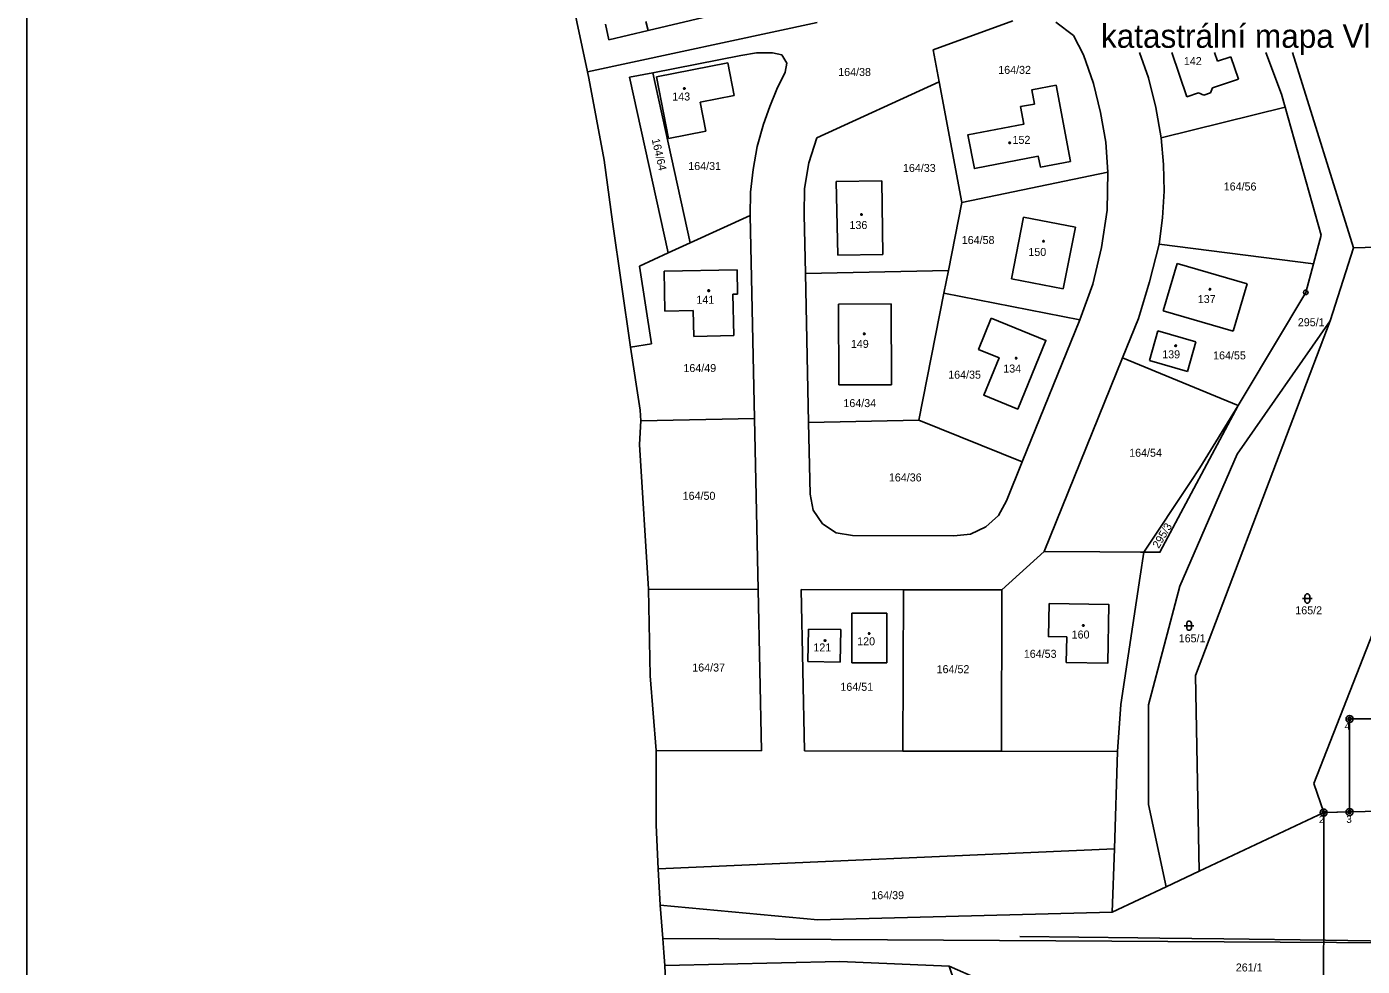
# Model space of a CAD drawing. Extents: x -779723 to -777378, y -1011169 to -1009297.
# Drawn here: x -779530.7 to -779247, y -1010479.3 to -1010279.6 of the extents above; entities that cross this region are included whole.
import ezdxf

# ---------------------------------------------------------------- set-up
doc = ezdxf.new("R2010")
doc.units = 0
for name, color, linetype in [('body', 7, 'Continuous'), ('cisla', 7, 'Continuous'), ('Default', 7, 'Continuous'), ('KN_HRANICE', 7, 'Continuous'), ('KN_KULTURY', 7, 'Continuous'), ('KN_PARCELY', 7, 'Continuous'), ('KN_VEDENI', 7, 'Continuous'), ('LEGENDA', 7, 'Continuous'), ('obvod_stavby', 7, 'Continuous'), ('Železniční svršek', 7, 'Continuous')]:
    doc.layers.add(name, color=color, linetype=linetype)

# ---------------------------------------------------------------- blocks, each defined once
blk = doc.blocks.new('316')
at = {"layer": 'Default'}
for points in [[(-1, 1), (0.27, 1), (1, 1)], [(-0.5, 1.5), (-0.4, 1.79), (-0.15, 1.97), (0.16, 1.97), (0.41, 1.79), (0.51, 1.5), (0.51, 0.5), (0.41, 0.21), (0.16, 0.03), (-0.15, 0.03), (-0.4, 0.21), (-0.5, 0.5), (-0.5, 1.5)]]:
    blk.add_lwpolyline(points, dxfattribs=at)
blk = doc.blocks.new('105')
at = {"layer": 'Default'}
blk.add_line((-0.12, 0), (0.12, 0), dxfattribs=at)
blk.add_lwpolyline([(0.15, 0.48), (0.4, 0.3), (0.5, 0.01), (0.4, -0.28), (0.15, -0.46), (-0.16, -0.46), (-0.41, -0.28), (-0.51, 0.01), (-0.41, 0.3), (-0.16, 0.48), (0.15, 0.48)], dxfattribs=at)
blk = doc.blocks.new('402')
at = {"layer": 'Default'}
blk.add_lwpolyline([(0.09, 0.15), (0.18, 0), (0.09, -0.15), (-0.09, -0.15), (-0.18, 0), (-0.09, 0.15), (0.09, 0.15)], dxfattribs=at)

msp = doc.modelspace()

# ---------------------------------------------------------------- linework, layer by layer
at = {"layer": 'body'}
for p, q in [((-779249.69, -1010426.74), (-779249.69, -1010426.74)), ((-779255.18, -1010446.63), (-779255.18, -1010446.63)), ((-779249.69, -1010446.5), (-779249.69, -1010446.5))]:
    msp.add_line(p, q, dxfattribs=at)
for centre, radius in [((-779249.69, -1010426.74), 0.75), ((-779249.69, -1010426.74), 0.35), ((-779255.18, -1010446.63), 0.75), ((-779255.18, -1010446.63), 0.35), ((-779249.69, -1010446.5), 0.75), ((-779249.69, -1010446.5), 0.35)]:
    msp.add_circle(centre, radius, dxfattribs=at)
at = {"layer": 'KN_HRANICE'}
for p, q in [((-779411.57, -1010289.24), (-779423.17, -1010234.28)), ((-779362.78, -1010278.71), (-779411.57, -1010289.24)), ((-779407.72, -1010279.08), (-779406.99, -1010282.4)), ((-779399.16, -1010278.51), (-779398.69, -1010280.44)), ((-779385.75, -1010277.38), (-779398.69, -1010280.44)), ((-779321.24, -1010278.36), (-779338.14, -1010284.55)), ((-779308.36, -1010281.51), (-779312.1, -1010278.67)), ((-779398.69, -1010280.44), (-779406.99, -1010282.4)), ((-779306.17, -1010285.63), (-779308.36, -1010281.51)), ((-779379.01, -1010285.72), (-779375.64, -1010285.2)), ((-779375.64, -1010285.2), (-779372.24, -1010285.16)), ((-779372.24, -1010285.16), (-779370.29, -1010285.62)), ((-779338.14, -1010284.55), (-779336.86, -1010291.37)), ((-779292.43, -1010290.53), (-779294.28, -1010285.09)), ((-779287.42, -1010285.09), (-779284.23, -1010294.51)), ((-779277.75, -1010286.96), (-779278.38, -1010285.09)), ((-779264.13, -1010293.98), (-779267.51, -1010285.09)), ((-779248.83, -1010326.61), (-779261.84, -1010285.09)), ((-779397.7, -1010289.41), (-779379.01, -1010285.72)), ((-779396.93, -1010290.27), (-779381.75, -1010287.29)), ((-779381.75, -1010287.29), (-779380.38, -1010294.23)), ((-779370.29, -1010285.62), (-779369.18, -1010287.35)), ((-779369.18, -1010287.35), (-779369.57, -1010289.31)), ((-779304.1, -1010291.71), (-779306.17, -1010285.63)), ((-779274.91, -1010286.01), (-779277.75, -1010286.96)), ((-779273.29, -1010290.79), (-779274.91, -1010286.01)), ((-779411.29, -1010290.56), (-779411.57, -1010289.24)), ((-779408.01, -1010308), (-779411.29, -1010290.56)), ((-779389.74, -1010325.58), (-779397.7, -1010289.41)), ((-779394.32, -1010303.41), (-779396.93, -1010290.27)), ((-779369.57, -1010289.31), (-779371.31, -1010292.92)), ((-779292.43, -1010290.53), (-779290.82, -1010296.83)), ((-779278.8, -1010292.6), (-779273.29, -1010290.79)), ((-779371.31, -1010292.92), (-779372.85, -1010296.61)), ((-779336.86, -1010291.37), (-779362.87, -1010303.27)), ((-779336.86, -1010291.37), (-779332.05, -1010316.98)), ((-779302.56, -1010297.89), (-779304.1, -1010291.71)), ((-779284.23, -1010294.51), (-779281.79, -1010293.68)), ((-779281.79, -1010293.68), (-779280.65, -1010294.17)), ((-779280.65, -1010294.17), (-779279.24, -1010293.68)), ((-779279.24, -1010293.68), (-779278.8, -1010292.6)), ((-779380.38, -1010294.23), (-779387.63, -1010295.67)), ((-779387.63, -1010295.67), (-779386.44, -1010301.84)), ((-779263.36, -1010296.74), (-779264.13, -1010293.98)), ((-779372.85, -1010296.61), (-779374.18, -1010300.38)), ((-779301.46, -1010304.17), (-779302.56, -1010297.89)), ((-779290.82, -1010296.83), (-779289.73, -1010303.24)), ((-779263.36, -1010296.74), (-779289.73, -1010303.24)), ((-779255.74, -1010323.95), (-779263.36, -1010296.74)), ((-779386.44, -1010301.84), (-779394.32, -1010303.41)), ((-779374.18, -1010300.38), (-779375.49, -1010305.12)), ((-779362.87, -1010303.27), (-779364.55, -1010308.53)), ((-779301, -1010310.57), (-779301.46, -1010304.17)), ((-779289.73, -1010303.24), (-779289.19, -1010308.89)), ((-779375.49, -1010305.12), (-779376.4, -1010309.95)), ((-779406.22, -1010321.12), (-779408.01, -1010308)), ((-779376.4, -1010309.95), (-779376.91, -1010314.83)), ((-779364.55, -1010308.53), (-779365.44, -1010313.99)), ((-779332.05, -1010316.98), (-779301, -1010310.57)), ((-779301.2, -1010318.61), (-779301, -1010310.57)), ((-779289.19, -1010308.89), (-779289.09, -1010314.57)), ((-779358.71, -1010312.55), (-779349.07, -1010312.38)), ((-779358.39, -1010328.18), (-779358.71, -1010312.55)), ((-779349.07, -1010312.38), (-779348.8, -1010328.01)), ((-779376.91, -1010314.83), (-779376.98, -1010319.73)), ((-779365.44, -1010313.99), (-779365.52, -1010319.51)), ((-779289.09, -1010314.57), (-779289.42, -1010320.24)), ((-779334.89, -1010331.42), (-779332.05, -1010316.98)), ((-779302.4, -1010326.55), (-779301.2, -1010318.61)), ((-779402.4, -1010347.73), (-779406.22, -1010321.12)), ((-779376.98, -1010319.73), (-779389.74, -1010325.58)), ((-779376.98, -1010319.73), (-779376.08, -1010362.91)), ((-779365.52, -1010319.51), (-779365.26, -1010332.05)), ((-779321.5, -1010333.19), (-779318.95, -1010320.1)), ((-779318.95, -1010320.1), (-779307.92, -1010322.25)), ((-779289.42, -1010320.24), (-779290.15, -1010325.87)), ((-779307.92, -1010322.25), (-779310.5, -1010335.33)), ((-779257.37, -1010330.02), (-779255.74, -1010323.95)), ((-779400.48, -1010330.51), (-779394.39, -1010327.71)), ((-779394.39, -1010327.71), (-779389.74, -1010325.58)), ((-779304.22, -1010334.38), (-779302.4, -1010326.55)), ((-779290.15, -1010325.87), (-779292.21, -1010333.83)), ((-779257.37, -1010330.02), (-779290.15, -1010325.87)), ((-779253.82, -1010342.15), (-779248.83, -1010326.61)), ((-779248.83, -1010326.61), (-779241.34, -1010326.4)), ((-779397.95, -1010347.05), (-779400.48, -1010330.51)), ((-779348.8, -1010328.01), (-779358.39, -1010328.18)), ((-779289.25, -1010340.01), (-779286.34, -1010329.98)), ((-779286.34, -1010329.98), (-779271.46, -1010334.31)), ((-779259, -1010336.11), (-779257.37, -1010330.02)), ((-779395.24, -1010331.56), (-779379.78, -1010331.29)), ((-779395.11, -1010340.07), (-779395.24, -1010331.56)), ((-779379.78, -1010331.29), (-779379.66, -1010336.48)), ((-779365.26, -1010332.05), (-779334.89, -1010331.42)), ((-779365.26, -1010332.05), (-779364.6, -1010363.75)), ((-779335.84, -1010336.25), (-779334.89, -1010331.42)), ((-779310.5, -1010335.33), (-779321.5, -1010333.19)), ((-779341.15, -1010363.28), (-779335.84, -1010336.25)), ((-779335.84, -1010336.25), (-779307.01, -1010341.91)), ((-779307.01, -1010341.91), (-779304.22, -1010334.38)), ((-779292.21, -1010333.83), (-779294.54, -1010341.64)), ((-779271.46, -1010334.31), (-779274.38, -1010344.34)), ((-779272.05, -1010357.97), (-779259, -1010336.11)), ((-779379.66, -1010336.48), (-779380.68, -1010336.5)), ((-779380.68, -1010336.5), (-779380.48, -1010345.29)), ((-779358.24, -1010338.57), (-779347.03, -1010338.54)), ((-779358.16, -1010355.75), (-779358.24, -1010338.57)), ((-779347.03, -1010338.54), (-779346.99, -1010355.72)), ((-779389.11, -1010339.96), (-779395.11, -1010340.07)), ((-779388.99, -1010345.45), (-779389.11, -1010339.96)), ((-779307.01, -1010341.91), (-779319.25, -1010372.13)), ((-779294.54, -1010341.64), (-779297.93, -1010350.03)), ((-779274.38, -1010344.34), (-779289.25, -1010340.01)), ((-779292.22, -1010350.54), (-779290.41, -1010344.29)), ((-779290.41, -1010344.29), (-779282.31, -1010346.63)), ((-779253.82, -1010342.15), (-779282.45, -1010417.52)), ((-779253.82, -1010342.15), (-779273.57, -1010370.48)), ((-779402.4, -1010347.73), (-779397.95, -1010347.05)), ((-779380.48, -1010345.29), (-779388.99, -1010345.45)), ((-779282.31, -1010346.63), (-779284.12, -1010352.88)), ((-779400.35, -1010361.15), (-779402.4, -1010347.73)), ((-779297.93, -1010350.03), (-779314.54, -1010391.18)), ((-779273.36, -1010360.11), (-779297.93, -1010350.03)), ((-779284.12, -1010352.88), (-779292.22, -1010350.54)), ((-779346.99, -1010355.72), (-779358.16, -1010355.75)), ((-779273.36, -1010360.11), (-779272.05, -1010357.97)), ((-779400.24, -1010363.41), (-779400.35, -1010361.15)), ((-779281.48, -1010373.4), (-779273.36, -1010360.11)), ((-779400.52, -1010368.39), (-779400.24, -1010363.41)), ((-779376.08, -1010362.91), (-779400.24, -1010363.41)), ((-779376.08, -1010362.91), (-779375.32, -1010399.25)), ((-779364.6, -1010363.75), (-779341.15, -1010363.28)), ((-779364.6, -1010363.75), (-779364.28, -1010378.98)), ((-779319.25, -1010372.13), (-779341.15, -1010363.28)), ((-779398.58, -1010399.19), (-779400.52, -1010368.39)), ((-779322.59, -1010380.37), (-779319.25, -1010372.13)), ((-779273.57, -1010370.48), (-779285.76, -1010398.5)), ((-779283.54, -1010376.5), (-779281.48, -1010373.4)), ((-779293.41, -1010391.29), (-779283.54, -1010376.5)), ((-779364.28, -1010378.98), (-779363.63, -1010382.4)), ((-779324.28, -1010383.52), (-779322.59, -1010380.37)), ((-779363.63, -1010382.4), (-779361.65, -1010385.29)), ((-779326.93, -1010385.93), (-779324.28, -1010383.52)), ((-779361.65, -1010385.29), (-779358.73, -1010387.21)), ((-779358.73, -1010387.21), (-779355.3, -1010387.79)), ((-779330.18, -1010387.47), (-779326.93, -1010385.93)), ((-779355.3, -1010387.79), (-779333.72, -1010387.84)), ((-779333.72, -1010387.84), (-779330.18, -1010387.47)), ((-779314.54, -1010391.18), (-779323.52, -1010399.33)), ((-779302.76, -1010391.24), (-779314.54, -1010391.18)), ((-779294.13, -1010391.29), (-779302.76, -1010391.24)), ((-779294.17, -1010396.39), (-779293.41, -1010391.29)), ((-779293.41, -1010391.29), (-779294.13, -1010391.29)), ((-779257.31, -1010440.46), (-779238.48, -1010392.35)), ((-779298.26, -1010423.68), (-779294.17, -1010396.39)), ((-779285.76, -1010398.5), (-779292.43, -1010423.76)), ((-779375.32, -1010399.25), (-779398.58, -1010399.19)), ((-779398.25, -1010417.61), (-779398.58, -1010399.19)), ((-779374.61, -1010433.5), (-779375.32, -1010399.25)), ((-779366.19, -1010399.24), (-779365.48, -1010433.52)), ((-779344.47, -1010399.29), (-779366.19, -1010399.24)), ((-779344.55, -1010433.56), (-779344.47, -1010399.29)), ((-779323.52, -1010399.33), (-779344.47, -1010399.29)), ((-779323.6, -1010433.61), (-779323.52, -1010399.33)), ((-779355.43, -1010414.78), (-779355.41, -1010404.25)), ((-779355.41, -1010404.25), (-779347.94, -1010404.25)), ((-779347.94, -1010404.25), (-779347.97, -1010414.8)), ((-779364.63, -1010407.66), (-779364.73, -1010414.54)), ((-779364.63, -1010407.66), (-779357.75, -1010407.71)), ((-779357.86, -1010414.64), (-779357.75, -1010407.71)), ((-779364.73, -1010414.54), (-779357.86, -1010414.64)), ((-779347.97, -1010414.8), (-779355.43, -1010414.78)), ((-779396.98, -1010433.44), (-779398.25, -1010417.61)), ((-779281.67, -1010459.12), (-779282.45, -1010417.52)), ((-779298.95, -1010433.67), (-779298.26, -1010423.68)), ((-779292.43, -1010423.76), (-779292.43, -1010444.9)), ((-779396.98, -1010433.44), (-779374.61, -1010433.5)), ((-779396.97, -1010449.31), (-779396.98, -1010433.44)), ((-779365.48, -1010433.52), (-779344.55, -1010433.56)), ((-779344.55, -1010433.56), (-779323.6, -1010433.61)), ((-779323.6, -1010433.61), (-779298.95, -1010433.67)), ((-779298.95, -1010433.67), (-779299.64, -1010454.37)), ((-779255.18, -1010446.63), (-779257.31, -1010440.46)), ((-779292.43, -1010444.9), (-779288.66, -1010462.42)), ((-779281.67, -1010459.12), (-779255.18, -1010446.63)), ((-779255.18, -1010446.63), (-779223.61, -1010445.86)), ((-779396.51, -1010458.6), (-779396.97, -1010449.31)), ((-779396.51, -1010458.6), (-779299.64, -1010454.37)), ((-779299.64, -1010454.37), (-779300.09, -1010467.81)), ((-779396.12, -1010466.31), (-779396.51, -1010458.6)), ((-779288.66, -1010462.42), (-779281.67, -1010459.12)), ((-779300.09, -1010467.81), (-779288.66, -1010462.42)), ((-779396.12, -1010466.31), (-779362.62, -1010469.45)), ((-779395.56, -1010473.38), (-779396.12, -1010466.31)), ((-779300.09, -1010467.81), (-779362.62, -1010469.45)), ((-779395.32, -1010476.34), (-779395.56, -1010473.38)), ((-779395.1, -1010479.15), (-779395.32, -1010476.34)), ((-779357.99, -1010478.29), (-779395.1, -1010479.15)), ((-779394.26, -1010499.5), (-779395.1, -1010479.15)), ((-779357.99, -1010478.29), (-779334.72, -1010479.27)), ((-779334.72, -1010479.27), (-779323.42, -1010512.4)), ((-779334.72, -1010479.27), (-779328.3, -1010482.13))]:
    msp.add_line(p, q, dxfattribs=at)
for points in [[(-779394.39, -1010327.71), (-779402.61, -1010290.38), (-779397.7, -1010289.41)], [(-779293.41, -1010391.29), (-779289.96, -1010391.32), (-779273.36, -1010360.11)]]:
    msp.add_lwpolyline(points, dxfattribs=at)
for points in [[(-779312.04, -1010292.07), (-779317.19, -1010293.07), (-779316.63, -1010296.07), (-779319.57, -1010296.61), (-779318.86, -1010300.34), (-779330.76, -1010302.6), (-779329.38, -1010309.79), (-779315.8, -1010307.17), (-779315.34, -1010309.48), (-779308.98, -1010308.25)], [(-779325.78, -1010341.59), (-779314.2, -1010346.31), (-779320.16, -1010360.9), (-779327.4, -1010357.94), (-779324.14, -1010349.97), (-779328.48, -1010348.2)], [(-779313.52, -1010402.22), (-779300.8, -1010402.42), (-779301.03, -1010414.86), (-779309.87, -1010414.71), (-779309.77, -1010409.3), (-779313.67, -1010409.23)]]:
    msp.add_lwpolyline(points, close=True, dxfattribs=at)
at = {"layer": 'KN_VEDENI'}
msp.add_line((-779395.56, -1010473.38), (-779130.44, -1010475.03), dxfattribs=at)
at = {"layer": 'LEGENDA'}
msp.add_lwpolyline([(-779530.66, -1010687.91), (-778936.66, -1010687.91), (-778936.66, -1010267.91), (-779530.66, -1010267.91)], close=True, dxfattribs=at)
at = {"layer": 'obvod_stavby'}
msp.add_lwpolyline([(-779249.69, -1010446.5), (-779249.69, -1010426.74), (-779238.66, -1010426.74), (-779242.1, -1010401.61), (-779239.48, -1010394.92), (-779235.13, -1010426.74), (-779233.15, -1010426.74), (-779223.61, -1010445.86), (-779200.73, -1010455.74), (-779202.13, -1010460.62), (-779207.48, -1010497.19), (-779226.1, -1010504.31), (-779235.46, -1010501.42), (-779255.21, -1010502.98), (-779255.18, -1010446.63), (-779249.69, -1010446.5)], dxfattribs=at)
at = {"layer": 'Železniční svršek'}
for p, q in [((-779294.64, -1010473.27), (-779319.74, -1010472.96)), ((-779289.98, -1010473.32), (-779294.64, -1010473.27)), ((-779276.41, -1010473.48), (-779289.98, -1010473.32)), ((-779254.8, -1010473.76), (-779276.41, -1010473.48)), ((-779233.21, -1010474.03), (-779254.8, -1010473.76))]:
    msp.add_line(p, q, dxfattribs=at)

# ---------------------------------------------------------------- block references
at = {"layer": 'KN_KULTURY'}
for name, p in [('402', (-779390.98, -1010292.78)), ('402', (-779321.89, -1010304.29)), ('402', (-779353.36, -1010319.55)), ('402', (-779314.71, -1010325.22)), ('402', (-779385.8, -1010335.73)), ('402', (-779352.77, -1010344.9)), ('402', (-779320.49, -1010350.07)), ('316', (-779258.67, -1010402.15)), ('402', (-779306.25, -1010406.86)), ('316', (-779283.79, -1010407.92)), ('402', (-779361.09, -1010410.08)), ('402', (-779351.72, -1010408.58))]:
    msp.add_blockref(name, p, dxfattribs=at)
at = {"layer": 'KN_KULTURY', "rotation": 100.78327600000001}
for p in [(-779279.33, -1010335.43), (-779286.65, -1010347.44)]:
    msp.add_blockref('402', p, dxfattribs=at)
at = {"layer": 'KN_PARCELY'}
msp.add_blockref('105', (-779259, -1010336.11), dxfattribs=at)

# ---------------------------------------------------------------- texts
at = {"layer": 'cisla'}
for s, p in [('  4', (-779251.9, -1010429.04)), ('  2', (-779257.36, -1010448.88)), ('  3', (-779251.53, -1010448.83))]:
    msp.add_text(s, height=1.552, dxfattribs=at).set_placement(p)
at = {"layer": 'KN_PARCELY'}
for s, p in [('164/32', (-779324.31, -1010289.66)), ('142', (-779284.89, -1010287.79)), ('164/38', (-779358.3, -1010290.11)), ('143', (-779393.55, -1010295.32)), ('152', (-779321.28, -1010304.53)), ('164/31', (-779390.15, -1010310.09)), ('164/33', (-779344.55, -1010310.5)), ('164/56', (-779276.42, -1010314.44)), ('136', (-779355.91, -1010322.63)), ('164/58', (-779332.06, -1010325.81)), ('150', (-779317.91, -1010328.35)), ('141', (-779388.42, -1010338.5)), ('137', (-779281.93, -1010338.36)), ('295/1', (-779260.68, -1010343.28)), ('149', (-779355.61, -1010347.89)), ('139', (-779289.48, -1010350.11)), ('164/55', (-779278.67, -1010350.33)), ('164/49', (-779391.18, -1010353.02)), ('164/35', (-779334.94, -1010354.43)), ('134', (-779323.24, -1010353.13)), ('164/34', (-779357.2, -1010360.47)), ('164/54', (-779296.5, -1010371.02)), ('164/36', (-779347.54, -1010376.27)), ('164/50', (-779391.34, -1010380.17)), ('165/2', (-779261.22, -1010404.5)), ('120', (-779354.27, -1010411.09)), ('160', (-779308.72, -1010409.65)), ('165/1', (-779285.98, -1010410.45)), ('121', (-779363.58, -1010412.4)), ('164/53', (-779318.88, -1010413.75)), ('164/37', (-779389.3, -1010416.66)), ('164/52', (-779337.4, -1010417.01)), ('164/51', (-779357.84, -1010420.76)), ('164/39', (-779351.27, -1010465.04)), ('261/1', (-779273.86, -1010480.4))]:
    msp.add_text(s, height=1.7, dxfattribs=at).set_placement(p)
for s, rotation, p in [('164/64', 283.041, (-779397.93, -1010303.59)), ('295/3', 59.301, (-779290.22, -1010390.64))]:
    msp.add_text(s, height=1.7, rotation=rotation, dxfattribs=at).set_placement(p)
at = {"layer": 'LEGENDA'}
msp.add_text('katastrální mapa Vlčí u Chlumčan', height=5, dxfattribs=at).set_placement((-779302.48, -1010284.12))

doc.saveas('drawing.dxf')
